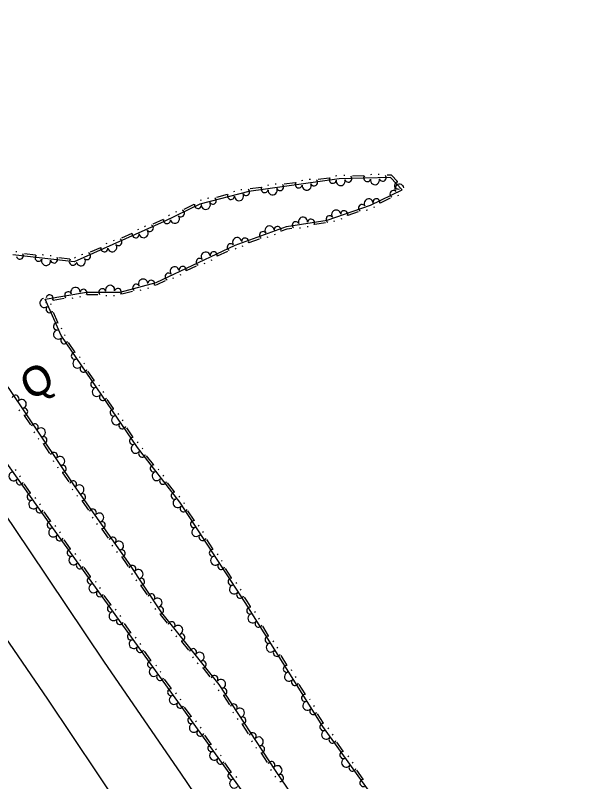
# Model space of a CAD drawing. Extents: x 2030130 to 2036320, y 723205 to 762423.
# Drawn here: x 2033171.6 to 2033381.3, y 761484.7 to 761768 of the extents above; entities that cross this region are included whole.
import ezdxf

# ---------------------------------------------------------------- set-up
doc = ezdxf.new("R2010")
doc.units = 0
for name, color, linetype in [('Draft_Station Cardinal Points', 7, 'Continuous'), ('Draft_Station Labels Major', 7, 'Continuous'), ('Draft_Station Tics Major', 7, 'Continuous'), ('Old_Level_15', 7, 'Continuous')]:
    doc.layers.add(name, color=color, linetype=linetype)

msp = doc.modelspace()

# ---------------------------------------------------------------- linework, layer by layer
at = {"layer": 'Draft_Station Labels Major'}
for points in [[(2033317.86, 761363.04), (2033290.43, 761403.19), (2033260.47, 761446.88), (2033232.75, 761487.83), (2033204.6, 761528.87), (2033176.73, 761570.42), (2033148.96, 761611.47), (2033120.54, 761652.92), (2033093.45, 761693.44), (2033064.45, 761735.88), (2033037.38, 761775.77), (2033009.06, 761817.74)], [(2032987.95, 761803.12), (2033043.65, 761720.79), (2033056.64, 761702.34), (2033057.8, 761696.58), (2033076.72, 761668.89), (2033082.75, 761662.9), (2033099.45, 761638.44), (2033127.47, 761597.33), (2033155.33, 761556.18), (2033183.52, 761515.12), (2033211.27, 761473.78), (2033239.33, 761432.83), (2033268.78, 761389.51), (2033297.27, 761347.85)]]:
    msp.add_lwpolyline(points, dxfattribs=at)
at = {"layer": 'Draft_Station Tics Major'}
for points in [[(2033068.77, 761781.86), (2033086.33, 761752.31), (2033109.9, 761713.34), (2033142.91, 761665.44), (2033169.42, 761629.65), (2033193.38, 761594), (2033213.28, 761565.74), (2033225.71, 761547.14), (2033246.82, 761520.6), (2033267.65, 761488.73), (2033286.08, 761461.77), (2033299.18, 761444.47), (2033317.3, 761416.96), (2033333.98, 761393.69), (2033349.54, 761371.11), (2033370.47, 761336.34), (2033381.34, 761317.53), (2033381.31, 761309.98), (2033376.82, 761308.9), (2033360.46, 761335.66), (2033268.79, 761462.78), (2033184.77, 761579.48), (2033107.4, 761688.4), (2033049.51, 761771.21)], [(2033303.28, 761709.1), (2033302.86, 761709.09)], [(2033306.15, 761709.18), (2033305.74, 761709.17)], [(2033312.85, 761706.54), (2033310.64, 761708.89), (2033309.03, 761708.85)], [(2033313, 761466.36), (2033285.32, 761505.1), (2033256.58, 761550.94), (2033232.38, 761587.97), (2033216.76, 761608.24), (2033188.52, 761649.59), (2033182.64, 761663.08), (2033197.98, 761665.6), (2033210.35, 761665.7), (2033223.72, 761669.26), (2033239.37, 761676.66), (2033252.84, 761683.02), (2033271.92, 761689.87), (2033286.95, 761692.33), (2033302.95, 761697.84), (2033314.59, 761703.48), (2033310.29, 761708.06), (2033291.31, 761707.54), (2033257.94, 761702.93), (2033239.8, 761698.23), (2033226.62, 761691.75), (2033193.36, 761676.86), (2033170.73, 761679.45)], [(2033275.06, 761706.12), (2033271, 761705.56)], [(2033277.84, 761706.92), (2033277.44, 761706.86)], [(2033280.69, 761707.31), (2033280.28, 761707.26)], [(2033287.65, 761707.86), (2033283.59, 761707.3)], [(2033290.44, 761708.66), (2033290.03, 761708.6)], [(2033293.44, 761708.83), (2033293.03, 761708.82)], [(2033300.42, 761708.61), (2033296.32, 761708.5)], [(2033255.41, 761703.54), (2033255.02, 761703.44)], [(2033262.46, 761704.38), (2033258.4, 761703.82)], [(2033265.25, 761705.18), (2033264.84, 761705.12)], [(2033268.09, 761705.57), (2033267.69, 761705.52)], [(2033315.11, 761704.73), (2033314.83, 761705.03)], [(2033249.96, 761701.71), (2033245.99, 761700.68)], [(2033252.64, 761702.82), (2033252.24, 761702.72)], [(2033306.59, 761698.69), (2033310.28, 761700.48)], [(2033313.04, 761701.36), (2033313.41, 761701.54)], [(2033237.64, 761698.08), (2033233.96, 761696.27)], [(2033240.33, 761699.64), (2033239.93, 761699.53)], [(2033243.1, 761700.36), (2033242.71, 761700.25)], [(2033231.2, 761695.37), (2033230.83, 761695.19)], [(2033294.64, 761694.11), (2033298.52, 761695.45)], [(2033301.37, 761695.99), (2033301.76, 761696.13)], [(2033304.18, 761697.07), (2033304.55, 761697.25)], [(2033226.25, 761692.48), (2033222.51, 761690.81)], [(2033228.62, 761694.1), (2033228.25, 761693.92)], [(2033289.35, 761691.86), (2033289.74, 761691.99)], [(2033292.06, 761692.79), (2033292.45, 761692.92)], [(2033219.72, 761690.01), (2033219.35, 761689.84)], [(2033269.99, 761688.31), (2033272.13, 761689.08), (2033273.79, 761689.35)], [(2033276.69, 761689.41), (2033277.09, 761689.47)], [(2033279.52, 761689.87), (2033279.92, 761689.94)], [(2033282.29, 761690.74), (2033286.33, 761691.4)], [(2033214.65, 761687.29), (2033210.91, 761685.61)], [(2033217.1, 761688.84), (2033216.73, 761688.67)], [(2033267.43, 761686.95), (2033267.81, 761687.09)], [(2033205.5, 761683.64), (2033205.13, 761683.47)], [(2033208.12, 761684.81), (2033207.75, 761684.65)], [(2033258.03, 761684.01), (2033261.89, 761685.4)], [(2033264.73, 761685.98), (2033265.11, 761686.12)], [(2033172.22, 761680.51), (2033171.81, 761680.56)], [(2033203.05, 761682.09), (2033199.3, 761680.42)], [(2033246.41, 761679.08), (2033250.12, 761680.83)], [(2033252.89, 761681.68), (2033253.26, 761681.86)], [(2033255.46, 761682.65), (2033255.85, 761682.79)], [(2033179.1, 761679.31), (2033175.03, 761679.78)], [(2033182, 761679.39), (2033181.59, 761679.44)], [(2033184.85, 761679.07), (2033184.45, 761679.11)], [(2033191.73, 761677.87), (2033187.66, 761678.33)], [(2033193.9, 761678.44), (2033193.52, 761678.28)], [(2033196.52, 761679.62), (2033196.14, 761679.45)], [(2033234.92, 761673.64), (2033238.62, 761675.4)], [(2033241.39, 761676.25), (2033241.77, 761676.43)], [(2033243.99, 761677.48), (2033244.36, 761677.65)], [(2033232.5, 761672.05), (2033232.87, 761672.22)], [(2033223.24, 761668.28), (2033224, 761668.48), (2033227.13, 761669.96)], [(2033229.9, 761670.82), (2033230.27, 761670.99)], [(2033217.8, 761666.41), (2033218.2, 761666.51)], [(2033220.57, 761667.14), (2033220.97, 761667.25)], [(2033195.41, 761663.93), (2033195.82, 761664)], [(2033198.05, 761664.78), (2033202.15, 761664.81)], [(2033205.03, 761664.42), (2033205.44, 761664.43)], [(2033207.89, 761664.45), (2033208.3, 761664.45)], [(2033210.96, 761665.01), (2033214.92, 761666.06)], [(2033182.87, 761661.87), (2033183.27, 761661.94)], [(2033184.91, 761660.96), (2033184.74, 761661.34)], [(2033185.63, 761662.74), (2033189.68, 761663.4)], [(2033192.58, 761663.46), (2033192.98, 761663.53)], [(2033187.31, 761654.41), (2033185.68, 761658.17)], [(2033188.84, 761651.94), (2033188.67, 761652.32)], [(2033190.01, 761649.59), (2033189.78, 761649.93)], [(2033193.6, 761643.6), (2033191.29, 761646.99)], [(2033195.56, 761641.46), (2033195.33, 761641.8)], [(2033197.18, 761639.09), (2033196.95, 761639.43)], [(2033200.77, 761633.1), (2033198.46, 761636.49)], [(2033202.73, 761630.96), (2033202.5, 761631.3)], [(2033204.35, 761628.59), (2033204.12, 761628.93)], [(2033207.94, 761622.6), (2033205.63, 761625.99)], [(2033172.98, 761622.15), (2033173.21, 761621.81)], [(2033174.92, 761619.99), (2033177.21, 761616.59)], [(2033209.9, 761620.46), (2033209.67, 761620.8)], [(2033211.52, 761618.09), (2033211.29, 761618.43)], [(2033215.11, 761612.1), (2033212.8, 761615.49)], [(2033178.47, 761613.98), (2033178.7, 761613.64)], [(2033180.07, 761611.6), (2033180.3, 761611.26)], [(2033217.07, 761609.96), (2033216.84, 761610.3)], [(2033182.01, 761609.44), (2033184.3, 761606.04)], [(2033218.72, 761607.7), (2033218.47, 761608.03)], [(2033222.66, 761601.93), (2033220.15, 761605.18)], [(2033185.56, 761603.43), (2033185.79, 761603.09)], [(2033171.88, 761599.75), (2033171.65, 761600.08)], [(2033187.16, 761601.04), (2033187.39, 761600.7)], [(2033189.1, 761598.89), (2033191.39, 761595.49)], [(2033224.73, 761599.91), (2033224.48, 761600.23)], [(2033173.55, 761597.41), (2033173.31, 761597.74)], [(2033226.48, 761597.64), (2033226.23, 761597.96)], [(2033177.25, 761591.49), (2033174.87, 761594.83)], [(2033192.68, 761592.86), (2033192.91, 761592.52)], [(2033230.42, 761591.86), (2033227.91, 761595.11)], [(2033194.33, 761590.51), (2033194.57, 761590.18)], [(2033232.49, 761589.84), (2033232.24, 761590.17)], [(2033179.25, 761589.38), (2033179.01, 761589.72)], [(2033180.91, 761587.04), (2033180.67, 761587.38)], [(2033196.32, 761588.4), (2033198.68, 761585.05)], [(2033234.21, 761587.42), (2033233.98, 761587.77)], [(2033184.61, 761581.12), (2033182.24, 761584.46)], [(2033237.68, 761581.36), (2033235.44, 761584.8)], [(2033200, 761582.47), (2033200.23, 761582.13)], [(2033186.61, 761579.03), (2033186.37, 761579.36)], [(2033201.65, 761580.12), (2033201.89, 761579.78)], [(2033239.59, 761579.18), (2033239.37, 761579.53)], [(2033188.29, 761576.7), (2033188.05, 761577.03)], [(2033203.64, 761578.01), (2033206, 761574.65)], [(2033241.16, 761576.78), (2033240.94, 761577.12)], [(2033192.03, 761570.8), (2033189.63, 761574.13)], [(2033244.63, 761570.72), (2033242.39, 761574.15)], [(2033207.32, 761572.07), (2033207.55, 761571.74)], [(2033194.04, 761568.71), (2033193.8, 761569.05)], [(2033208.97, 761569.72), (2033209.21, 761569.39)], [(2033210.96, 761567.61), (2033212.6, 761565.28), (2033213.28, 761564.26)], [(2033246.55, 761568.54), (2033246.32, 761568.88)], [(2033195.72, 761566.38), (2033195.48, 761566.72)], [(2033248.12, 761566.14), (2033247.89, 761566.48)], [(2033199.46, 761560.49), (2033197.06, 761563.81)], [(2033214.54, 761561.65), (2033214.76, 761561.3)], [(2033251.59, 761560.08), (2033249.34, 761563.51)], [(2033201.47, 761558.4), (2033201.23, 761558.73)], [(2033216.13, 761559.26), (2033216.36, 761558.92)], [(2033203.14, 761556.07), (2033202.9, 761556.4)], [(2033218.07, 761557.1), (2033220.34, 761553.69)], [(2033253.5, 761557.9), (2033253.28, 761558.24)], [(2033206.89, 761550.17), (2033204.49, 761553.5)], [(2033255.07, 761555.5), (2033254.85, 761555.84)], [(2033221.6, 761551.07), (2033221.83, 761550.73)], [(2033258.51, 761549.4), (2033257.27, 761551.38), (2033256.3, 761552.87)], [(2033208.9, 761548.08), (2033208.66, 761548.41)], [(2033223.19, 761548.69), (2033223.42, 761548.35)], [(2033260.39, 761547.18), (2033260.17, 761547.53)], [(2033210.57, 761545.75), (2033210.33, 761546.08)], [(2033225.18, 761546.48), (2033227.74, 761543.27)], [(2033261.91, 761544.75), (2033261.69, 761545.1)], [(2033214.31, 761539.85), (2033211.92, 761543.18)], [(2033265.27, 761538.63), (2033263.09, 761542.1)], [(2033229.2, 761540.77), (2033229.46, 761540.45)], [(2033216.32, 761537.76), (2033216.08, 761538.09)], [(2033230.99, 761538.52), (2033231.24, 761538.2)], [(2033233.1, 761536.53), (2033235.65, 761533.32)], [(2033267.14, 761536.42), (2033266.92, 761536.76)], [(2033218, 761535.43), (2033217.76, 761535.76)], [(2033268.66, 761533.98), (2033268.45, 761534.33)], [(2033221.74, 761529.53), (2033219.34, 761532.86)], [(2033237.12, 761530.82), (2033237.37, 761530.5)], [(2033272.02, 761527.86), (2033269.84, 761531.33)], [(2033223.75, 761527.44), (2033223.51, 761527.78)], [(2033238.9, 761528.58), (2033239.16, 761528.26)], [(2033225.43, 761525.11), (2033225.19, 761525.45)], [(2033241.01, 761526.58), (2033243.57, 761523.38)], [(2033273.89, 761525.64), (2033273.68, 761525.99)], [(2033229.17, 761519.22), (2033226.77, 761522.54)], [(2033275.42, 761523.21), (2033275.2, 761523.56)], [(2033245.03, 761520.87), (2033245.29, 761520.55)], [(2033278.77, 761517.08), (2033276.59, 761520.56)], [(2033231.18, 761517.13), (2033230.94, 761517.46)], [(2033246.64, 761518.64), (2033246.86, 761518.29)], [(2033248.55, 761516.46), (2033250.79, 761513.03)], [(2033232.86, 761514.8), (2033232.62, 761515.13)], [(2033280.65, 761514.87), (2033280.43, 761515.22)], [(2033236.6, 761508.9), (2033234.2, 761512.23)], [(2033282.17, 761512.44), (2033281.95, 761512.79)], [(2033252.02, 761510.4), (2033252.24, 761510.06)], [(2033253.59, 761507.99), (2033253.82, 761507.65)], [(2033285.53, 761506.31), (2033283.35, 761509.79)], [(2033238.61, 761506.81), (2033238.37, 761507.14)], [(2033255.5, 761505.82), (2033257.75, 761502.38)], [(2033240.28, 761504.48), (2033240.04, 761504.81)], [(2033287.46, 761504.22), (2033287.22, 761504.56)], [(2033289.12, 761501.89), (2033288.89, 761502.22)], [(2033244.03, 761498.58), (2033241.63, 761501.91)], [(2033258.98, 761499.75), (2033259.2, 761499.41)], [(2033292.84, 761495.98), (2033290.46, 761499.32)], [(2033246.04, 761496.49), (2033245.8, 761496.82)], [(2033260.54, 761497.35), (2033260.77, 761497.01)], [(2033247.71, 761494.16), (2033247.47, 761494.49)], [(2033262.46, 761495.17), (2033264.7, 761491.74)], [(2033294.85, 761493.88), (2033294.61, 761494.21)], [(2033251.45, 761488.26), (2033249.06, 761491.59)], [(2033296.52, 761491.55), (2033296.28, 761491.88)], [(2033265.93, 761489.11), (2033266.15, 761488.77)], [(2033300.24, 761485.64), (2033297.85, 761488.97)], [(2033253.46, 761486.17), (2033253.23, 761486.51)], [(2033267.54, 761486.71), (2033267.77, 761486.37)]]:
    msp.add_lwpolyline(points, dxfattribs=at)
for centre, radius, start, end in [((2033276.39, 761705.48), 1.3, 148.6321, 349.4287), ((2033282.08, 761706.26), 1.3, 206.2986, 47.0951), ((2033288.98, 761707.22), 1.3, 148.6321, 349.4287), ((2033291.85, 761706.73), 1.69, 167.5458, 15.6182), ((2033294.7, 761707.63), 1.3, 200.0169, 40.8135), ((2033301.67, 761707.82), 1.3, 142.3505, 343.147), ((2033304.56, 761707.08), 1.69, 167.5458, 15.6182), ((2033307.41, 761707.98), 1.3, 200.0169, 40.8135), ((2033313.09, 761705.08), 1.3, 93.9591, 294.7556), ((2033256.91, 761702.66), 1.3, 212.9596, 53.7562), ((2033263.8, 761703.74), 1.3, 148.6321, 349.4287), ((2033266.75, 761703.32), 1.69, 173.8274, 21.8999), ((2033269.48, 761704.52), 1.3, 206.2986, 47.0951), ((2033279.34, 761705.06), 1.69, 173.8274, 21.8999), ((2033311.4, 761701.93), 1.3, 44.2966, 245.0931), ((2033313.62, 761703.92), 1.69, 11.8254, 219.8978), ((2033244.61, 761699.47), 1.3, 212.9596, 53.7562), ((2033251.35, 761701.22), 1.3, 155.2931, 356.0897), ((2033254.34, 761701.15), 1.69, 180.4884, 28.5609), ((2033239.1, 761697.89), 1.3, 166.9457, 7.7423), ((2033242.03, 761697.96), 1.69, 180.4884, 28.5609), ((2033299.8, 761696.76), 1.3, 37.426, 238.2225), ((2033302.25, 761698.47), 1.69, 4.9548, 213.0273), ((2033305.12, 761698.89), 1.3, 346.6301, 187.4267), ((2033232.85, 761694.81), 1.3, 224.6122, 65.4088), ((2033290.23, 761694.33), 1.69, 4.9548, 213.0273), ((2033293.21, 761694.49), 1.3, 339.7595, 180.5561), ((2033227.69, 761692.28), 1.3, 166.9457, 7.7423), ((2033230.63, 761692.81), 1.69, 192.141, 40.2135), ((2033277.97, 761691.7), 1.69, 355.2587, 203.3312), ((2033280.94, 761691.35), 1.3, 330.0634, 170.86), ((2033287.78, 761692.62), 1.3, 37.426, 238.2225), ((2033221.35, 761689.39), 1.3, 222.5584, 63.3549), ((2033265.58, 761688.47), 1.69, 5.7216, 213.794), ((2033268.56, 761688.66), 1.3, 340.5263, 181.3228), ((2033275.27, 761690.42), 1.3, 27.7299, 228.5264), ((2033216.11, 761687.04), 1.3, 164.8919, 5.6885), ((2033219.06, 761687.47), 1.69, 190.0872, 38.1597), ((2033263.15, 761686.72), 1.3, 38.1927, 238.9893), ((2033209.75, 761684.19), 1.3, 222.5584, 63.3549), ((2033251.25, 761682.27), 1.3, 43.7212, 244.5178), ((2033253.61, 761684.17), 1.69, 5.7216, 213.794), ((2033256.59, 761684.37), 1.3, 340.5263, 181.3228), ((2033204.51, 761681.85), 1.3, 164.8919, 5.6885), ((2033207.46, 761682.27), 1.69, 190.0872, 38.1597), ((2033244.95, 761679.29), 1.3, 346.0548, 186.8513), ((2033173.3, 761679.15), 1.3, 191.9095, 32.7061), ((2033180.23, 761678.36), 1.3, 134.2431, 335.0396), ((2033182.99, 761677.22), 1.69, 159.4383, 7.5108), ((2033185.94, 761677.71), 1.3, 191.9095, 32.7061), ((2033192.86, 761676.91), 1.3, 134.2431, 335.0396), ((2033195.86, 761677.08), 1.69, 190.0872, 38.1597), ((2033198.14, 761679), 1.3, 222.5584, 63.3549), ((2033239.76, 761676.84), 1.3, 43.7212, 244.5178), ((2033242, 761678.81), 1.69, 11.25, 219.3225), ((2033230.51, 761673.37), 1.69, 11.2679, 219.3403), ((2033233.46, 761673.86), 1.3, 346.0726, 186.8691), ((2033228.26, 761671.41), 1.3, 43.7391, 244.5356), ((2033218.86, 761668.81), 1.69, 0.8759, 208.9484), ((2033221.84, 761668.76), 1.3, 335.6806, 176.4772), ((2033193.86, 761665.75), 1.69, 355.2919, 203.3644), ((2033196.83, 761665.41), 1.3, 330.0966, 170.8932), ((2033203.79, 761665.64), 1.3, 18.8833, 219.6798), ((2033206.65, 761666.49), 1.69, 346.4121, 194.4846), ((2033209.53, 761665.69), 1.3, 321.2168, 162.0134), ((2033216.29, 761667.28), 1.3, 33.3471, 234.1437), ((2033184.29, 761663.35), 1.3, 330.0966, 170.8932), ((2033191.17, 761664.48), 1.3, 27.7631, 228.5597), ((2033182.37, 761661.65), 1.69, 99.5132, 307.5857), ((2033184.27, 761659.34), 1.3, 131.9844, 332.781), ((2033187.05, 761652.95), 1.3, 74.318, 275.1145), ((2033187.45, 761649.99), 1.69, 99.5132, 307.5857), ((2033189.69, 761647.88), 1.3, 142.7662, 343.5628), ((2033193.62, 761642.12), 1.3, 85.0998, 285.8963), ((2033194.56, 761639.29), 1.69, 110.2951, 318.3675), ((2033196.86, 761637.38), 1.3, 142.7662, 343.5628), ((2033200.79, 761631.62), 1.3, 85.0998, 285.8963), ((2033201.73, 761628.79), 1.69, 110.2951, 318.3675), ((2033171.71, 761626.24), 1.3, 322.3359, 163.1325), ((2033204.03, 761626.88), 1.3, 142.7662, 343.5628), ((2033173.99, 761624.31), 1.69, 289.8647, 137.9372), ((2033174.91, 761621.47), 1.3, 264.6694, 105.466), ((2033207.96, 761621.12), 1.3, 85.0998, 285.8963), ((2033208.9, 761618.29), 1.69, 110.2951, 318.3675), ((2033178.8, 761615.69), 1.3, 322.3359, 163.1325), ((2033181.09, 761613.76), 1.69, 289.8647, 137.9372), ((2033211.2, 761616.38), 1.3, 142.7662, 343.5628), ((2033182.01, 761610.92), 1.3, 264.6694, 105.466), ((2033215.13, 761610.62), 1.3, 85.0998, 285.8963), ((2033216.1, 761607.75), 1.69, 113.5881, 321.6606), ((2033185.89, 761605.13), 1.3, 322.3359, 163.1325), ((2033188.18, 761603.21), 1.69, 289.8647, 137.9372), ((2033218.5, 761605.98), 1.3, 146.0593, 346.8559), ((2033189.1, 761600.37), 1.3, 264.6694, 105.466), ((2033222.76, 761600.46), 1.3, 88.3928, 289.1894), ((2033170.92, 761597.56), 1.69, 111.3505, 319.423), ((2033223.86, 761597.68), 1.69, 113.5881, 321.6606), ((2033173.26, 761595.69), 1.3, 143.8217, 344.6183), ((2033192.99, 761594.58), 1.3, 322.3359, 163.1325), ((2033226.26, 761595.91), 1.3, 146.0593, 346.8559), ((2033195.3, 761592.7), 1.69, 291.1202, 139.1927), ((2033177.29, 761590.01), 1.3, 86.1552, 286.9518), ((2033196.28, 761589.88), 1.3, 265.9249, 106.7215), ((2033230.52, 761590.39), 1.3, 88.3928, 289.1894), ((2033178.29, 761587.19), 1.69, 111.3505, 319.423), ((2033231.6, 761587.67), 1.69, 109.1271, 317.1996), ((2033180.62, 761585.33), 1.3, 143.8217, 344.6183), ((2033200.29, 761584.18), 1.3, 323.5914, 164.388), ((2033233.85, 761585.72), 1.3, 141.5983, 342.3949), ((2033202.62, 761582.3), 1.69, 291.1202, 139.1927), ((2033184.66, 761579.64), 1.3, 86.1552, 286.9518), ((2033203.6, 761579.49), 1.3, 265.9249, 106.7215), ((2033237.67, 761579.88), 1.3, 83.9318, 284.7284), ((2033238.55, 761577.03), 1.69, 109.1271, 317.1996), ((2033185.67, 761576.83), 1.69, 111.7161, 319.7886), ((2033188.01, 761574.98), 1.3, 144.1873, 344.9839), ((2033240.81, 761575.08), 1.3, 141.5983, 342.3949), ((2033207.61, 761573.79), 1.3, 323.5914, 164.388), ((2033209.94, 761571.91), 1.69, 291.1202, 139.1927), ((2033192.08, 761569.33), 1.3, 86.5208, 287.3174), ((2033210.92, 761569.09), 1.3, 265.9249, 106.7215), ((2033244.62, 761569.24), 1.3, 83.9318, 284.7284), ((2033193.09, 761566.52), 1.69, 111.7161, 319.7886), ((2033245.5, 761566.39), 1.69, 109.1271, 317.1996), ((2033195.44, 761564.67), 1.3, 144.1873, 344.9839), ((2033214.88, 761563.35), 1.3, 322.1804, 162.9769), ((2033247.76, 761564.44), 1.3, 141.5983, 342.3949), ((2033217.15, 761561.42), 1.69, 289.7092, 137.7817), ((2033199.51, 761559.01), 1.3, 86.5208, 287.3174), ((2033218.06, 761558.58), 1.3, 264.5139, 105.3105), ((2033251.57, 761558.6), 1.3, 83.9318, 284.7284), ((2033200.52, 761556.2), 1.69, 111.7161, 319.7886), ((2033252.46, 761555.75), 1.69, 109.1271, 317.1996), ((2033202.87, 761554.35), 1.3, 144.1873, 344.9839), ((2033221.94, 761552.78), 1.3, 322.1804, 162.9769), ((2033254.72, 761553.79), 1.3, 141.5983, 342.3949), ((2033224.21, 761550.85), 1.69, 289.7092, 137.7817), ((2033206.94, 761548.69), 1.3, 86.5208, 287.3174), ((2033207.95, 761545.88), 1.69, 111.7161, 319.7886), ((2033225.13, 761548.01), 1.3, 264.5139, 105.3105), ((2033258.47, 761547.92), 1.3, 82.8537, 283.6503), ((2033210.29, 761544.03), 1.3, 144.1873, 344.9839), ((2033259.3, 761545.05), 1.69, 108.049, 316.1215), ((2033229.4, 761542.5), 1.3, 326.9442, 167.7407), ((2033231.83, 761540.76), 1.69, 294.473, 142.5455), ((2033261.52, 761543.06), 1.3, 140.5202, 341.3167), ((2033214.37, 761538.37), 1.3, 86.5208, 287.3174), ((2033232.97, 761538.01), 1.3, 269.2777, 110.0743), ((2033215.38, 761535.56), 1.69, 111.7161, 319.7886), ((2033265.23, 761537.15), 1.3, 82.8537, 283.6503), ((2033217.72, 761533.71), 1.3, 144.1873, 344.9839), ((2033237.31, 761532.55), 1.3, 326.9442, 167.7407), ((2033266.06, 761534.28), 1.69, 108.049, 316.1215), ((2033239.74, 761530.82), 1.69, 294.473, 142.5455), ((2033268.28, 761532.28), 1.3, 140.5202, 341.3167), ((2033221.8, 761528.06), 1.3, 86.5208, 287.3174), ((2033240.89, 761528.06), 1.3, 269.2777, 110.0743), ((2033271.98, 761526.38), 1.3, 82.8537, 283.6503), ((2033222.81, 761525.25), 1.69, 111.7161, 319.7886), ((2033272.81, 761523.51), 1.69, 108.049, 316.1215), ((2033225.15, 761523.4), 1.3, 144.1873, 344.9839), ((2033245.23, 761522.6), 1.3, 326.9442, 167.7407), ((2033247.68, 761520.79), 1.69, 289.1245, 137.197), ((2033275.03, 761521.51), 1.3, 140.5202, 341.3167), ((2033248.56, 761517.94), 1.3, 263.9292, 104.7258), ((2033229.22, 761517.74), 1.3, 86.5208, 287.3174), ((2033230.23, 761514.93), 1.69, 111.7161, 319.7886), ((2033278.73, 761515.61), 1.3, 82.8537, 283.6503), ((2033232.58, 761513.08), 1.3, 144.1873, 344.9839), ((2033252.38, 761512.1), 1.3, 321.5957, 162.3922), ((2033279.56, 761512.74), 1.69, 108.049, 316.1215), ((2033254.63, 761510.15), 1.69, 289.1245, 137.197), ((2033281.78, 761510.74), 1.3, 140.5202, 341.3167), ((2033236.65, 761507.42), 1.3, 86.5208, 287.3174), ((2033255.52, 761507.29), 1.3, 263.9292, 104.7258), ((2033237.66, 761504.61), 1.69, 111.7161, 319.7886), ((2033285.5, 761504.85), 1.3, 86.3189, 287.1155), ((2033240.01, 761502.76), 1.3, 144.1873, 344.9839), ((2033259.33, 761501.46), 1.3, 321.5957, 162.3922), ((2033286.5, 761502.03), 1.69, 111.5142, 319.5867), ((2033261.59, 761499.5), 1.69, 289.1245, 137.197), ((2033288.84, 761500.17), 1.3, 143.9854, 344.7819), ((2033244.08, 761497.1), 1.3, 86.5208, 287.3174), ((2033262.47, 761496.65), 1.3, 263.9292, 104.7258), ((2033245.09, 761494.29), 1.69, 111.7161, 319.7886), ((2033292.89, 761494.5), 1.3, 86.3189, 287.1155), ((2033247.43, 761492.44), 1.3, 144.1873, 344.9839), ((2033266.29, 761490.81), 1.3, 321.5957, 162.3922), ((2033293.89, 761491.69), 1.69, 111.5142, 319.5867), ((2033251.51, 761486.79), 1.3, 86.5208, 287.3174), ((2033268.54, 761488.88), 1.69, 290.3192, 138.3917), ((2033296.23, 761489.83), 1.3, 143.9854, 344.7819), ((2033252.52, 761483.98), 1.69, 111.7161, 319.7886), ((2033269.48, 761486.05), 1.3, 265.1239, 105.9205), ((2033300.28, 761484.16), 1.3, 86.3189, 287.1155)]:
    msp.add_arc(centre, radius, start, end, dxfattribs=at)

# ---------------------------------------------------------------- texts
at = {"layer": 'Draft_Station Cardinal Points'}
msp.add_text('O', height=10.66, rotation=25.7434, dxfattribs=at).set_placement((2033176.81, 761625.54))
at = {"layer": 'Old_Level_15'}
msp.add_text('Q', height=10.66, rotation=25.7434, dxfattribs=at).set_placement((2033176.92, 761625.87))

doc.saveas('drawing.dxf')
